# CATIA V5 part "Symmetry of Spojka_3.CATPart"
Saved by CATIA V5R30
Part number: Symmetry of Spojka_3
Bounding box of the stored display mesh (mm): x -8.66 to 8.66, y -7.5 to 7.5, z -9 to 17
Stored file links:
  E:\Bakalarka\Model\Forma_v7\Symmetry of Spojka_3.CATPart
  E:\Bakalarka\Model\Forma_v7\Spojka_1.CATPart
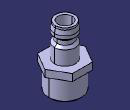
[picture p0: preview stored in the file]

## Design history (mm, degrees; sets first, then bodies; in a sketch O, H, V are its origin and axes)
Body1 (main body)
  Body2 "Body from original PartBody"
    Solid1: linked copy from another document
  Assemble1: tool Body2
